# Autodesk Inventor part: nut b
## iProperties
Author: Rich
Shininess: 20.0
PropertySet Name: _Private Model Information
Created: 2001-04
Part Number: nut b
Document SubType Name: Modeling
Designer: Rich
Control State: 0
Master: False
Checked Out: False
PropertySet Name: Design Tracking Control
Density: 0.0
Volumn: 0.0
Area: 0.0
PropertySet Name: Model Information
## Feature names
1. Base1
2. Extrusion1
3. Hole1
4. Chamfer1
5. Extrusion2
6. Fillet1
